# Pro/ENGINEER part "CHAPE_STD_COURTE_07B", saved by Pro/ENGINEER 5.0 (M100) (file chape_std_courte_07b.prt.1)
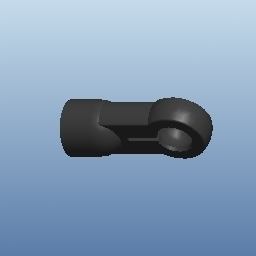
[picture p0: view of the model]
Units: millimeter Newton Second (mmNs); MM, TONNE, HOURS
Materials in the file: NYLON

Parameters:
  PTC_MATERIAL_NAME = "NYLON"

Other named items: DROITE, DESSUS, FACE, CHAPE_STD_COURTE_07B

Layers: 02_POINTS, 03_PLANS, 05_SURFACES, 06_REPERES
